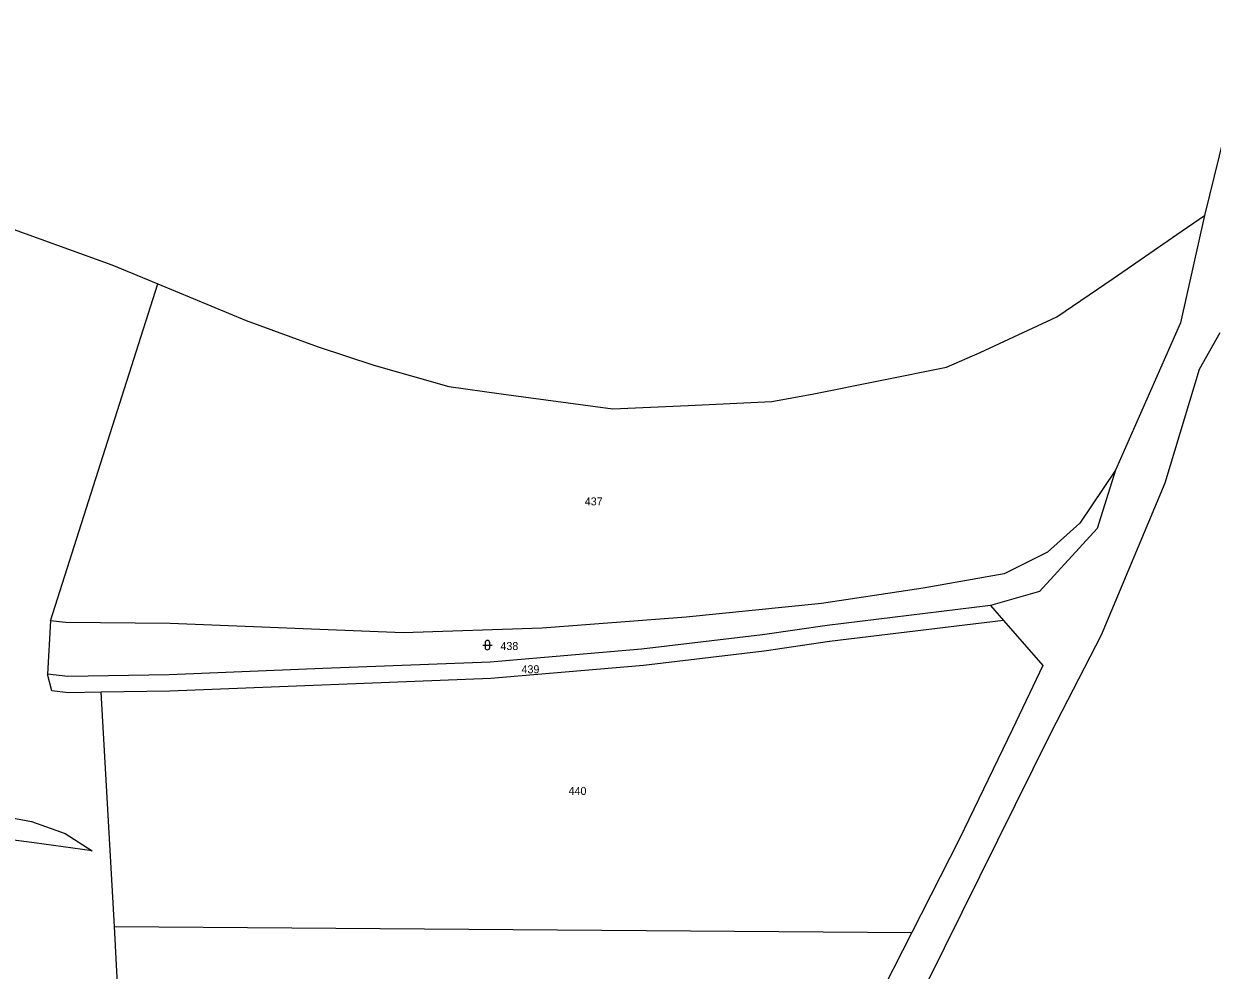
# Model space of a CAD drawing. Extents: x -769392 to -767038, y -1018329 to -1015269.
# Drawn here: x -768286.9 to -768034.4, y -1015766.2 to -1015565.2 of the extents above; entities that cross this region are included whole.
import ezdxf

# ---------------------------------------------------------------- set-up
doc = ezdxf.new("R2010")
doc.units = 0
doc.header["$LTSCALE"] = 0.68
doc.layers.add('1', color=7, linetype='Continuous', lineweight=25)
doc.layers.add('3', color=7, linetype='Continuous', lineweight=25)
doc.layers.add('2', color=7, linetype='Continuous')

msp = doc.modelspace()

# ---------------------------------------------------------------- linework, layer by layer
at = {"layer": '1'}
for p, q in [((-768026.1, -1015565.25), (-768036.1, -1015605.96)), ((-768297.46, -1015605.86), (-768268.23, -1015616.42)), ((-768041.97, -1015610.01), (-768036.1, -1015605.96)), ((-768055.51, -1015619.37), (-768041.97, -1015610.01)), ((-768268.23, -1015616.42), (-768258.45, -1015620.48)), ((-768281.27, -1015692.06), (-768258.45, -1015620.48)), ((-768258.45, -1015620.48), (-768239.69, -1015628.27)), ((-768067.45, -1015627.5), (-768055.51, -1015619.37)), ((-768083.72, -1015635.05), (-768067.45, -1015627.5)), ((-768239.69, -1015628.27), (-768224.38, -1015633.83)), ((-768224.38, -1015633.83), (-768212.59, -1015637.71)), ((-768090.91, -1015638.14), (-768083.72, -1015635.05)), ((-768212.59, -1015637.71), (-768196.6, -1015642.3)), ((-768119.07, -1015643.81), (-768090.91, -1015638.14)), ((-768196.6, -1015642.3), (-768185.55, -1015643.81)), ((-768185.55, -1015643.81), (-768161.81, -1015646.99)), ((-768145.78, -1015646.27), (-768128, -1015645.48)), ((-768128, -1015645.48), (-768119.07, -1015643.81)), ((-768161.81, -1015646.99), (-768145.78, -1015646.27)), ((-768081.56, -1015688.79), (-768078.77, -1015691.98)), ((-768281.27, -1015692.06), (-768281.92, -1015703.32)), ((-768267.7, -1015756.93), (-768270.5, -1015707.2)), ((-768265.13, -1015802.54), (-768267.7, -1015756.93)), ((-768267.7, -1015756.93), (-768098.24, -1015758.2))]:
    msp.add_line(p, q, dxfattribs=at)
for points in [[(-768036.1, -1015605.96), (-768041.21, -1015628.76), (-768055, -1015660.04)], [(-768102.72, -1015799.16), (-768102.1, -1015790.03), (-768098.18, -1015776.92), (-768095.07, -1015769.01), (-768068.74, -1015715.9), (-768057.97, -1015694.98), (-768044.47, -1015662.72), (-768037.18, -1015638.56), (-768032.78, -1015630.79)], [(-768055, -1015660.04), (-768062.57, -1015671.3), (-768069.41, -1015677.46), (-768078.67, -1015682.02), (-768095.87, -1015685.11), (-768117.49, -1015688.35), (-768146.18, -1015691.23), (-768176.83, -1015693.61), (-768206.33, -1015694.59), (-768255.81, -1015692.62), (-768278.08, -1015692.37), (-768281.27, -1015692.06)], [(-768055, -1015660.04), (-768058.92, -1015672.45), (-768071.12, -1015685.8), (-768081.56, -1015688.79)], [(-768081.56, -1015688.79), (-768116.28, -1015692.99), (-768130.02, -1015694.97), (-768155.69, -1015698.03), (-768187.85, -1015700.8), (-768223.38, -1015702.14), (-768256.07, -1015703.49), (-768277.6, -1015703.85), (-768281.92, -1015703.32)], [(-768078.77, -1015691.98), (-768115.78, -1015696.45), (-768129.61, -1015698.45), (-768155.28, -1015701.51), (-768187.72, -1015704.3), (-768255.93, -1015706.99), (-768270.5, -1015707.2)], [(-768078.77, -1015691.98), (-768070.4, -1015701.52), (-768076.89, -1015715.06), (-768088.2, -1015738.46), (-768098.24, -1015758.2)], [(-768270.5, -1015707.2), (-768277.54, -1015707.32), (-768281.01, -1015706.89), (-768281.92, -1015703.32)], [(-768293.69, -1015733.05), (-768285.3, -1015734.67), (-768278.12, -1015737.17), (-768272.38, -1015740.87), (-768284.71, -1015739.14), (-768331.53, -1015733.07)], [(-768098.24, -1015758.2), (-768106.1, -1015773.64), (-768110.79, -1015788.45), (-768112.9, -1015796.24)]]:
    msp.add_lwpolyline(points, dxfattribs=at)
at = {"layer": '3'}
for p, q in [((-768189.441, -1015697.181), (-768187.439, -1015697.181)), ((-768188.941, -1015696.681), (-768188.941, -1015697.682)), ((-768187.939, -1015697.682), (-768187.939, -1015696.681))]:
    msp.add_line(p, q, dxfattribs=at)
for centre, start, end in [((-768188.44, -1015696.6809), 0, 180), ((-768188.44, -1015697.6809), 180, 359.98789)]:
    msp.add_arc(centre, 0.5, start, end, dxfattribs=at)

# ---------------------------------------------------------------- texts
at = {"layer": '2'}
for s, p in [('437', (-768167.75, -1015667.515)), ('438', (-768185.67, -1015698.225)), ('439', (-768181.19, -1015703.155)), ('440', (-768171.19, -1015728.995))]:
    msp.add_text(s, height=1.7, dxfattribs=at).set_placement(p)

doc.saveas('drawing.dxf')
